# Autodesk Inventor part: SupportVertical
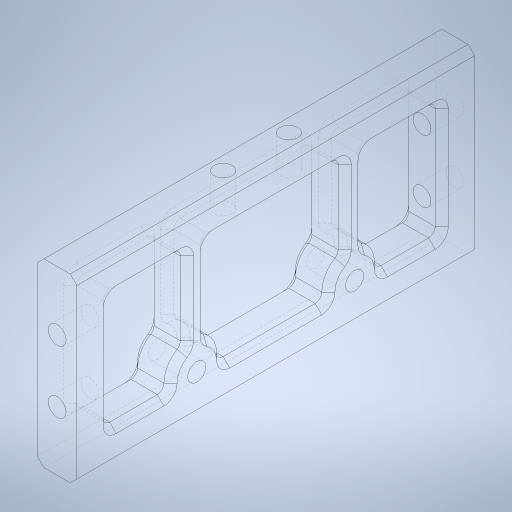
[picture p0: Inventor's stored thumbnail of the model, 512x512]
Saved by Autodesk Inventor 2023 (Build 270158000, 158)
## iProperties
Created: 2023-10
Part Number: SupportVertical
Material: Aluminum 7075
Document SubType Name: Modeling
Designer: tornqvih
Density: 2.81 g/cm^3
Appearance: Satin - Brushed Heavy
Mass: 139.831 g
Surface Area: 196.874 cm^2
Volume: 49.7618 cm^3
Author: tornqvih
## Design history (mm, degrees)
sketch "Sketch1"
  geometry: L1 (-27.5, 60.5)-(27.5, 60.5); L2 (27.5, 60.5)-(27.5, -60.5); L3 (27.5, -60.5)-(-27.5, -60.5); L4 (-27.5, -60.5)-(-27.5, 60.5); L5 (-27.5, 60.5)-(27.5, -60.5); L6 (27.5, 60.5)-(-27.5, -60.5); 1 further point
  constraints: 12 end point, 2 midpoint, 2 parallel, 1 horizontal, 1 perpendicular
  dimensions: "d0" = 121 distance of L1.end L2.end; "d1" = 55 distance of L1.start L1.end
extrude "Extrusion1" new body sketch "Sketch1" distance "d2" = 12; taper "d3" = 0 deg
sketch "Sketch2"
  geometry: L1 (-50.5, 17.5)-(50.5, 17.5); L2 (50.5, 17.5)-(50.5, -17.5); L3 (50.5, -17.5)-(-50.5, -17.5); L4 (-50.5, -17.5)-(-50.5, 17.5); L5 (0, -38.5)-(0, 38.5) reference; L6 (84.7, 0)-(-84.7, 0) reference; L7 (60.5, 27.5)-(-60.5, 27.5) reference; L8 (-60.5, 27.5)-(-60.5, -27.5) reference; L9 (-60.5, -27.5)-(60.5, -27.5) reference; L10 (60.5, -27.5)-(60.5, 27.5) reference; 2 further points
  constraints: 8 end point, 2 parallel, 2 point on line, 2 symmetric about line, 1 horizontal, 1 perpendicular
  dimensions: "d4" = 10 distance between parallel lines of L7 L1; "d5" = 10 distance between parallel lines of L8 L4; "d52" = 10 distance between parallel lines of L9 L3; "d54" = 10 distance between parallel lines of L10 L2
extrude "Extrusion2" cut sketch "Sketch2" extent not by distance; stored distance "d9" = 10; taper "d10" = 0 deg
sketch "Sketch7"
  geometry: L1 (-40, 0)-(30, 0) reference; L2 (-27.5, 60.5)-(-27.5, -60.5) reference; L3 (17.5, -50.5)-(17.5, 50.5) reference; L4 (17.5, 27)-(-8.084, 27); L5 (17.5, 21)-(-8.084, 21); L6 (17.5, -21)-(-8.084, -21); L7 (17.5, -27)-(-8.084, -27); C1 r 8 at (-15.5, -24); A1 r 8 centre (-15.5, 24) between (-8.084, 27) and (-8.084, 21); 5 further points
  constraints: 8 end point, 5 symmetric about line, 2 centre point, 2 point on circle, 2 point on line, 1 parallel, 1 perpendicular
  dimensions: "d55" = 16 diameter of A1; "d56" = 24 distance from line of L1 A1.centre; "d57" = 12 distance from line of L2 A1.centre; "d58" = 3 distance from line of A1.centre L4; "d59" = 3 distance from line of A1.centre L5; "d60" = 16 diameter of C1
extrude "Extrusion3" join sketch "Sketch7" distance "d61" = 12; taper "d62" = 0 deg
sketch "Sketch3"
  geometry: L1 (0, 55)-(0, 0) reference; L2 (0, 55)-(12, 55) reference; L3 (0, 0)-(12, 0) reference; 3 further points
  constraints: 1 vertical alignment
  dimensions: "d12" = 6 distance from line of L1 point (6, 37); "d13" = 18 distance from line of L2 point (6, 37); "d14" = 18 distance from line of L3 point (6, 18)
hole "Hole1" sketch "Sketch3" at (6, 37), (6, 18) diameter "d15" = 5.5; stored, may be unused: countersink angle "d19" = 90 deg, drill point angle "d21" = 118 deg; dims "d16" = 6, "d17" = 4, "d18" = 2, "d20" = 10
sketch "Sketch4"
  geometry: C1 r 2.75 at (-6, 37) reference; C2 r 2.75 at (-6, 18) reference; 2 further points
  constraints: 2 coincident
hole "Hole2" sketch "Sketch4" at (-6, 37), (-6, 18) diameter "d25" = 5.5; stored, may be unused: countersink angle "d29" = 90 deg, drill point angle "d31" = 118 deg; dims "d26" = 6, "d27" = 4, "d28" = 2, "d30" = 10
sketch "Sketch5"
  geometry: L1 (0, 121)-(0, 0) reference; 5 further points
  constraints: 2 vertical alignment, 1 horizontal alignment, 1 midpoint
  dimensions: "d32" = 6 distance from line of L1 point (6, 60.5); "d33" = 10 distance of point (6, 50.5) point (6, 60.5); "d34" = 10 distance of point (6, 70.5) point (6, 60.5)
hole "Hole3" sketch "Sketch5" at (6, 50.5), (6, 70.5) diameter "d35" = 5.5; stored, may be unused: countersink angle "d39" = 90 deg, drill point angle "d41" = 118 deg; dims "d36" = 6, "d37" = 4, "d38" = 2, "d40" = 10
sketch "Sketch6"
  geometry: L1 (0, -38.5)-(0, 38.5) reference; L2 (-60.5, -27.5)-(60.5, -27.5) reference; 3 further points
  constraints: 1 symmetric about line
  dimensions: "d44" = 12 distance from line of L2 point (-24, -15.5); "d63" = 24 distance from line of L1 point (-24, -15.5)
hole "Hole4" sketch "Sketch6" at (-24, -15.5), (24, -15.5) diameter "d45" = 5.5; stored, may be unused: countersink angle "d49" = 90 deg, drill point angle "d51" = 118 deg; dims "d46" = 6, "d47" = 4, "d48" = 2, "d50" = 10
fillet "Fillet1" dims "d64" = 2
chamfer "Chamfer1" distance "d66" = 2; stored, may be unused: second distance "d67" = 2, angle "d68" = 45 deg
body "Solid1"
